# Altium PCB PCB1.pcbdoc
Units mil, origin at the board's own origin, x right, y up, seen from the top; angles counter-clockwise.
Board outline 1100 x 2012.93 mil, 2 copper layers (Top Layer, Bottom Layer); 25 components, 17 nets, 61 pads, 18 vias.
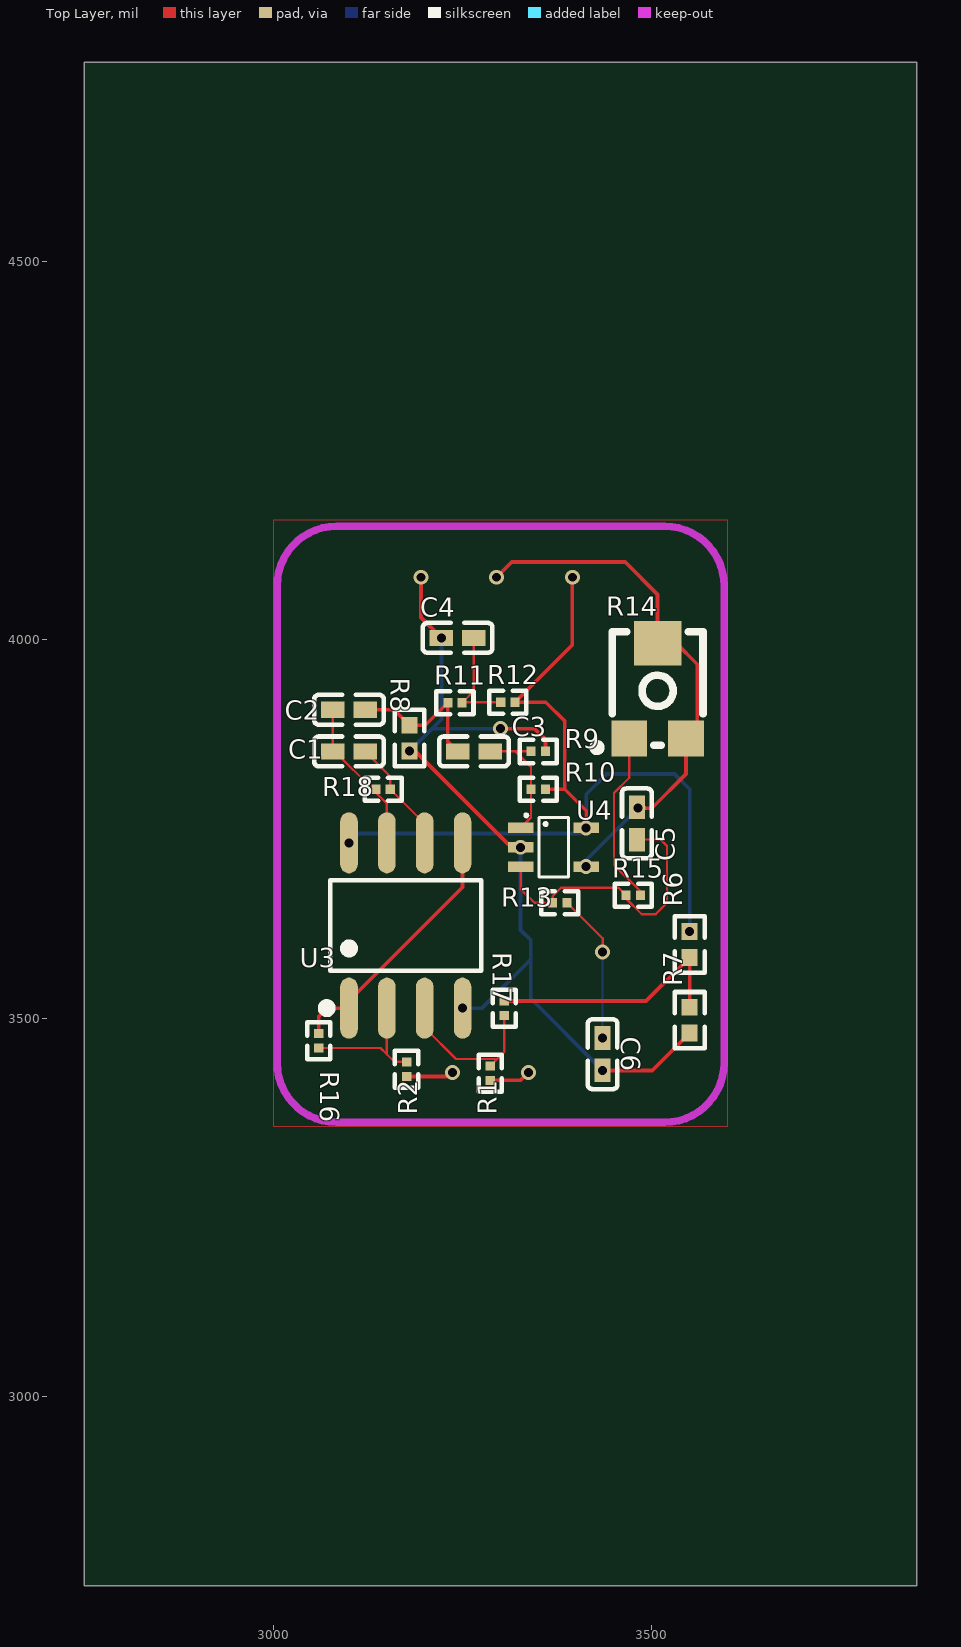
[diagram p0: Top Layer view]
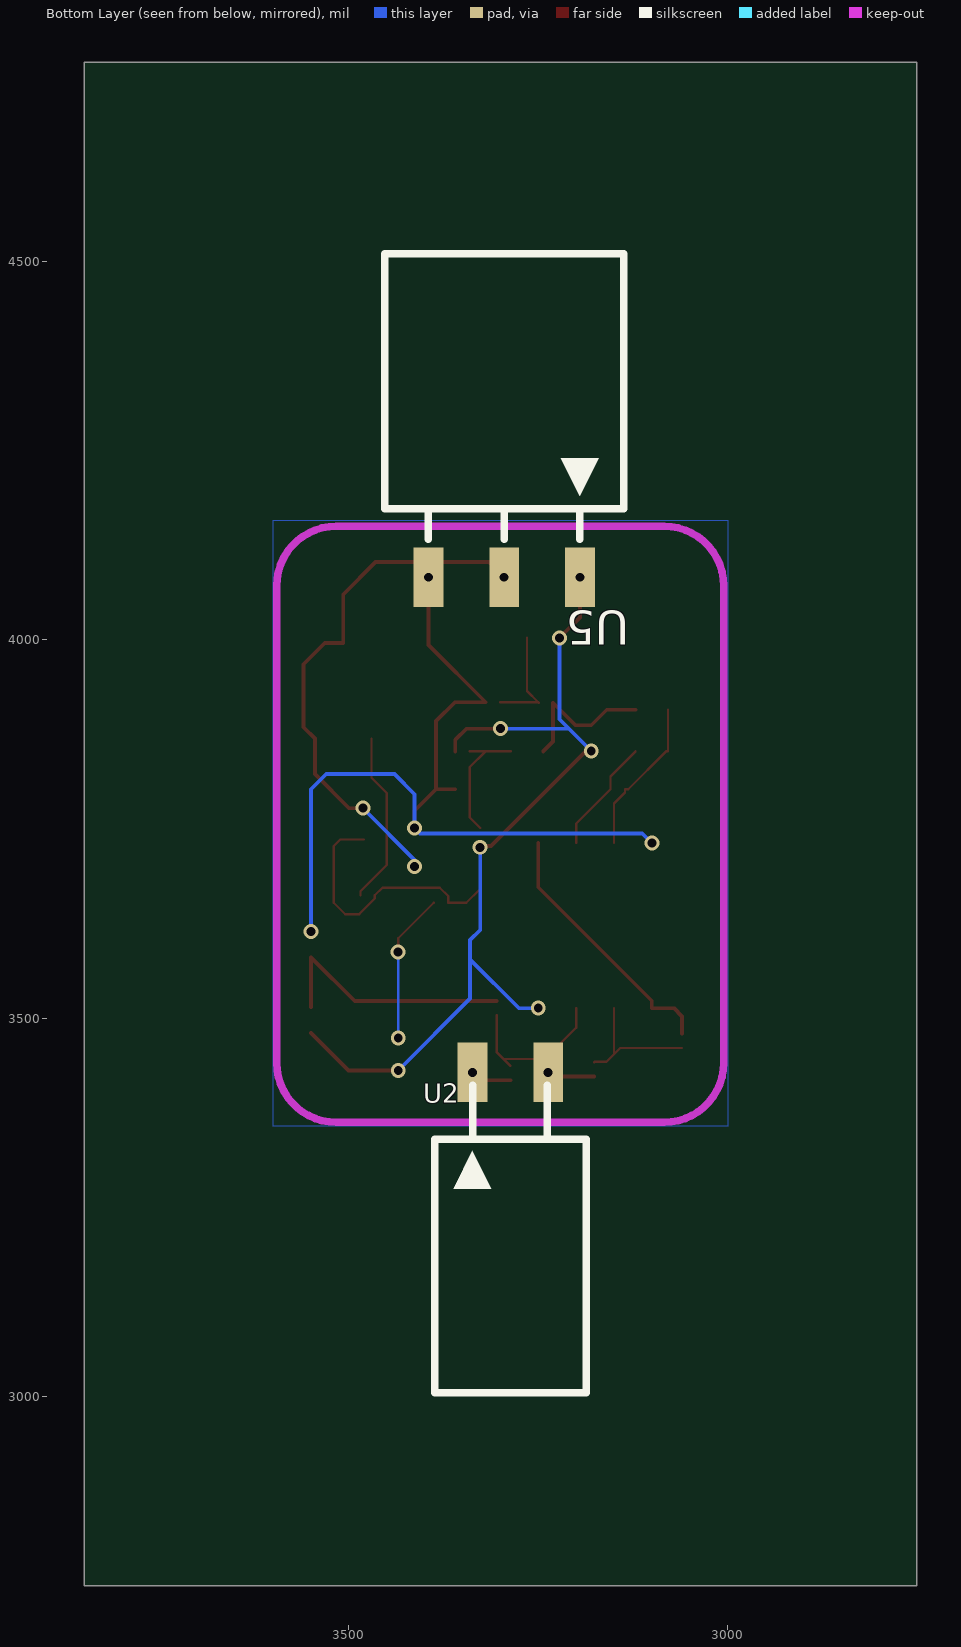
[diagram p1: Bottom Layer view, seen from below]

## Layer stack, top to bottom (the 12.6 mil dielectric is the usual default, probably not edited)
Top Layer: signal copper (thickness not stored)
Dielectric: dielectric 12.6, FR-4, Dk 4.8
Bottom Layer: signal copper (thickness not stored)

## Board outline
3850,2750 2750,2750 2750,4762.93 3850,4762.93

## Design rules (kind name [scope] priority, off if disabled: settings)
Clearance copperThickness1oz [All] p1: gap=7 ignorepadtopadclearanceinfootprint=FALSE except(4: Track-Track; 6: Track-SMDPad SMDPad-SMDPad Track-THPad SMDPad-THPad THPad-THPad Track-Via SMDPad-Via THPad-Via Via-Via Track-Fill SMDPad-Fill THPad-Fill Via-Fill Fill-Fill SMDPad-Region THPad-Region Via-Region Fill-Region Region-Region Track-Poly SMDPad-Poly THPad-Poly Via-Poly Fill-Poly Poly-Poly Track-Text SMDPad-Text THPad-Text Via-Text Fill-Text Region-Text Poly-Text Text-Text Track-Hole SMDPad-Hole THPad-Hole Via-Hole Fill-Hole Region-Hole Poly-Hole Text-Hole; 11.8: Track-Region Region-Poly Track-Sheet SMDPad-Sheet THPad-Sheet Via-Sheet Fill-Sheet Region-Sheet Poly-Sheet Text-Sheet Sheet-Hole)
Clearance copperThickness2oz [All] p1: gap=7 ignorepadtopadclearanceinfootprint=FALSE except(6: Track-SMDPad SMDPad-SMDPad Track-THPad SMDPad-THPad THPad-THPad Track-Via SMDPad-Via THPad-Via Via-Via Track-Fill SMDPad-Fill THPad-Fill Via-Fill Fill-Fill SMDPad-Region THPad-Region Via-Region Fill-Region Region-Region Track-Poly SMDPad-Poly THPad-Poly Via-Poly Fill-Poly Poly-Poly Track-Text SMDPad-Text THPad-Text Via-Text Fill-Text Region-Text Poly-Text Text-Text Track-Hole SMDPad-Hole THPad-Hole Via-Hole Fill-Hole Region-Hole Poly-Hole Text-Hole; 8: Track-Track; 11.8: Track-Region Region-Poly Track-Sheet SMDPad-Sheet THPad-Sheet Via-Sheet Fill-Sheet Region-Sheet Poly-Sheet Text-Sheet Sheet-Hole)
DiffPairsRouting differentialPair [All] p1: maxuncoupledlength=10 maxlimit=6 mostfreqgap=6 toplayer_minwidth=5 toplayer_prefwidth=10 toplayer_maxwidth=100 bottomlayer_minwidth=5 bottomlayer_prefwidth=10 bottomlayer_maxwidth=100
PasteMaskExpansion pasteMaskExpansion [All] p1:
PlaneConnect innerPlane [All] p1: planeconnectstyle=Relief reliefexpansion=20 reliefentries=4 reliefconductorwidth=10 reliefairgap=10
PolygonConnect copperRegion [All] p1: connectstyle=Relief reliefentries=4 reliefconductorwidth=10 polygonreliefangle="90 Angle" airgapwidth=10
RoutingVias viaSize [All] p1: viastyle="Through Hole" holewidth=11.8 minholewidth=11.8 maxholewidth=248 width=19.7 minwidth=19.7 maxwidth=393.7
SolderMaskExpansion solderMaskExpansion [All] p1: useseparateexpansions=TRUE expansion=2 expansionbottom=2
Width copperThickness1oz [All] p1: maxlimit=4 minlimit=3 preferedwidth=4
Width copperThickness2oz [All] p1: maxlimit=6 minlimit=5 preferedwidth=6

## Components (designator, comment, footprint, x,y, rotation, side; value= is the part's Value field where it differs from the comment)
C1 "CC0402JRNPO9BN100" C0402 3100,3852.38 r180 top
C2 "CL05A105KP5NNNC" C0402 3100,3907.38 r0 top
C3 "CC0402KRX7R9BB103" C0402 3265,3852.38 r0 top
C4 "CC0402KRX7R7BB104" C0402 3243.47,4002.38 r0 top
C5 "GRM1555C1H101JA01D" C0402 3480.22,3757.38 r90 top
C6 "GRM155R60J106ME44D" C0402 3434.96,3452.38 r90 top
R1 "0201WMF1002TEE" R0201 3286.53,3427.38 r90 top
R2 "0201WMF1002TEE" R0201 3176.07,3432.38 r90 top
R6 "0402WGF3001TCE" R0402 3550,3597.38 r90 top
R7 "0402WGF1001TCE" R0402 3550,3497.38 r90 top
R8 "0402WGF8201TCE" R0402 3180,3869.92 r90 top
R9 "RC0201FR-071ML" R0201 3350,3852.38 r180 top
R10 "RC0201FR-071ML" R0201 3350,3802.38 r0 top
R11 "0201WMF1001TEE" R0201 3240,3916.72 r0 top
R12 "0201WMF1001TEE" R0201 3309.95,3917.38 r0 top
R13 "0201WMF1001TEE" R0201 3378.51,3652.38 r180 top
R14 "TC33X-2-104E" RES-ADJ-SMD_TC33X-2-104E 3507.63,3932.38 r0 top
R15 "RC0201FR-0722KL" R0201 3475.37,3662.38 r0 top
R16 "RC0201FR-07200KL" R0201 3060,3470.1 r90 top
R17 "RC0201FR-07200KL" R0201 3305,3513.23 r270 top
R18 "0201WMF2004TEE" R0201 3145,3802.38 r180 top
U2 "X6511FRS-02-C85D30" HDR-SMD_2P-P2.54-H-F-L11.5 3286.89,3428.5 r180 bottom
U3 "LM358BAIDR" SOIC-8_L4.9-W3.9-P1.27-LS6.0-BL 3175,3622.38 r0 top
U4 "MAX4466EXK+T" SC-70-5_L2.0-W1.3-P0.65-LS2.1-BR 3370,3725.72 r180 top
U5 "X6511FRS-03-C85D30" HDR-SMD_3P-P2.54-H-F-L11.5 3295,4082.38 r0 bottom

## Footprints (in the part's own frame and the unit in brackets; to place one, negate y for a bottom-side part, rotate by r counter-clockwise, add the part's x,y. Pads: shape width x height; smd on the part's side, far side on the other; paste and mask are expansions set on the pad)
C0402 [mm]
  rect 0.79x0.54 smd: 1(-0.545,0) 2(0.545,0)
  silkscreen extent -1.17,-0.5 1.17,0.5
HDR-SMD_2P-P2.54-H-F-L11.5 [mm]
  rect 1x2 smd: 1(-1.27,0) 2(1.27,0)
  silkscreen extent -2.54,-10.76 2.54,-0.43
HDR-SMD_3P-P2.54-H-F-L11.5 [mm]
  rect 1x2 smd: 1(-2.54,0) 2(0,0) 3(2.54,0)
  silkscreen extent -4.01,-10.86 4.01,-1.27
R0201 [mil]
  rect 11.93x12.76 smd: 1(-9.51,0) 2(9.51,0)
  silkscreen extent -24,-15 24,15
R0402 [mm]
  rect 0.566x0.54 smd: 1(-0.433,0) 2(0.433,0)
  silkscreen extent -0.94,-0.5 0.94,0.5
RES-ADJ-SMD_TC33X-2-104E [mm]
  rect 1.2x1.2 smd: 1(-0.95,-1.6) 3(0.95,-1.6)
  rect 1.6x1.5 smd: 2(0,1.6)
  silkscreen extent -2.16,-2.03 1.52,1.98
SC-70-5_L2.0-W1.3-P0.65-LS2.1-BR [mm]
  rect 0.85x0.35 smd: 1(1.1,-0.65) 2(1.1,0) 3(1.1,0.65) 4(-1.1,0.65) 5(-1.1,-0.65)
  silkscreen extent -0.5,-1.12 0.96,1
SOIC-8_L4.9-W3.9-P1.27-LS6.0-BL [mm]
  oval 0.588x2.045 smd: 1(-1.905,-2.772) 2(-0.635,-2.772) 3(0.635,-2.772) 4(1.905,-2.772) 5(1.905,2.772) 6(0.635,2.772) 7(-0.635,2.772) 8(-1.905,2.772)
  silkscreen extent -2.8,-2.92 2.53,1.52

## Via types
v1: diameter 19.7, hole 11.81, Top Layer to Bottom Layer, 17 vias
v2: diameter 19.68, hole 11.81, Top Layer to Bottom Layer, 1 vias

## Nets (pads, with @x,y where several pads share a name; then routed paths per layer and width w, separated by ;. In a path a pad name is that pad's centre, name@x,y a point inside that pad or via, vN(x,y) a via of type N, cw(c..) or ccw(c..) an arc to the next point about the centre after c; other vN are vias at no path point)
$1N688: R1.2 R17.2 U3.3 | length 213.2
  Top Layer w3: U3.3 3200,3487.38 3241.24,3446.14 3295.78,3446.14 ; R1.2 3295.78,3446.14 ; R17.2 3305,3455.35 3295.78,3446.14
$1N766: R2.2 R16.1 U3.2 | length 184.7
  Top Layer w3: R16.1 3141.79,3460.59 3150,3452.38 ; U3.2 3150,3452.38 ; R2.2 3175.59,3442.38 3160,3442.38 3150,3452.38
$1N988: C1.1 R18.1 U3.6 | length 153.4
  Top Layer w3: C1.1 3154.51,3819.33 R18.1 3200,3756.89 U3.6
$1N2751: C4.2 R11.2 R12.1 | length 142.3
  Top Layer w3: R11.2 R11.2@3250.17,3917.38 ; C4.2 3264.93,3932.14 R11.2@3250.17,3917.38 ; R12.1 R11.2@3250.17,3917.38
$1N2818: C3.2 R9.2 R10.1 U4.1 | length 169.4
  Top Layer w3: C3.2 3319.8,3852.38 ; U4.1 3340.49,3765.11 R10.1 3340.49,3831.69 3319.8,3852.38 ; R9.2 3319.8,3852.38
$1N3169: C6.2 R13.1 | length 198
  Top Layer w3: R13.1 3435,3605.4 v1(3435,3587.38)
  Bottom Layer w3: v1(3434.96,3473.84) v1@3434.96,3587.34
$1N3329: C5.1 R13.2 R15.1 U4.3 | length 385.4
  Top Layer w3: U4.3 3326.69,3670.69 3345,3652.38 R13.2 3369,3661.38 3380,3672.38 3455.86,3672.38 R15.1 3465.86,3658.14 3486.62,3637.38 3505,3637.38 3520,3652.38 3520,3727.38 3511.46,3735.92 C5.1
$1N3336: R14.1 R15.2 | length 229.8
  Top Layer w3: R14.1 3470.23,3817.61 3450,3797.38 3450,3702.38 3484.88,3667.5 R15.2
$1N3656: C1.2 C2.1 R18.2 U3.7 | length 209.5
  Top Layer w3: C2.1 C1.2 3081.25,3852.38 3131.25,3802.38 R18.2 3135.49,3798.14 3150,3783.63 U3.7
AGND: C4.1 C6.1 R7.1 R8.1 R9.1 U3.4 U4.2 U5.1 | length 1219.9
  Top Layer w5: v1(3180,3852.88) 3187.07,3852.88 3312.58,3727.38 3325.03,3727.38 v1(3326.69,3725.72) ; v1(3195,4082.38) 3195,4029.38 v1(3222.01,4002.38) ; v1(3300,3882.38) 3345,3882.38 3359.51,3867.87 R9.1 ; v1(3434.96,3430.92) 3500.58,3430.92 R7.1
  Bottom Layer w5: v1(3180,3852.88) 3210.76,3883.64 ; v1(3222.01,4002.38) 3222.01,3894.89 3210.76,3883.64 ; v1(3250,3513.23) 3275.85,3513.23 3340,3577.38 ; v1(3300,3882.38) 3212.02,3882.38 3210.76,3883.64 ; v1(3326.69,3725.72) 3326.69,3616.54 3340,3603.23 3340,3577.38 ; v1(3434.96,3430.92) 3340,3525.88 3340,3577.38
V_F: C2.2 C3.1 R8.2 R11.1 | length 199.6
  Top Layer w5: C2.2 3159.59,3907.38 R8.2 3200.73,3886.96 R11.1 3230.49,3865.43 C3.1
V_OUT: C5.2 R14.2 R14.3 U4.4 U5.2 | length 707.7
  Top Layer w5: v1(3295,4082.38) 3315,4102.38 3465,4102.38 3507.63,4059.75 R14.2 3532.01,3995.37 3560,3967.38 3560,3884.35 R14.3 3545.03,3822.41 3500,3777.38 v1(3481.68,3777.38) C5.2
  Bottom Layer w5: v1(3413.31,3700.13) 3413.31,3709.01 v1(3481.68,3777.38)
V_REF: R6.1 R7.2 R17.1 | length 334.8
  Top Layer w5: R17.1 3492.41,3522.74 R6.1 R7.2
VCC: R6.2 R10.2 R12.2 U3.8 U4.5 U5.3 | length 1160.3
  Top Layer w5: R10.2 3385,3802.38 ; v1(3395,4082.38) 3395,3992.92 R12.2 3360,3917.38 3385,3892.38 3385,3802.38 ; v1(3413.31,3751.31) 3413.31,3774.07 3385,3802.38
  Bottom Layer w5: v1(3100,3731.53) 3112.54,3744.07 3406.07,3744.07 v1(3413.31,3751.31) 3413.31,3795.69 3440,3822.38 3530,3822.38 3550,3802.38 v1(3550,3614.42)
VIN1: R2.1 U2.2 | length 63.1
  Top Layer w5: R2.1 3231.26,3422.87 v1(3236.89,3428.5)
VIN2: 
VO1: R16.2 U3.1 U3.5 | length 347.7
  Top Layer w5: R16.2 3060,3502.38 3070.85,3513.23 U3.1 3100,3523.04 3250,3673.04 U3.5
pads on no net: R1.1 U2.1
copper on no net: | length 54.8
  Top Layer w5: 3286.53,3417.87 3326.26,3417.87 v2(3336.89,3428.5)

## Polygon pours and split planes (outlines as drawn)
AGND on Top Layer (solid, remove dead copper): 3000,3357.38 3600,3357.38 3600,4157.38 3000,4157.38
AGND on Bottom Layer (solid, remove dead copper, pour order 4): 3000,3357.38 3600,3357.38 3600,4157.38 3000,4157.38

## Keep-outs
Board Outline Layer:
  lines w10: 3005,3441.12 ccw(c3083.74,3441.12) 3083.74,3362.38 3516.81,3362.38 ccw(c3516.81,3441.12) 3595.55,3441.12 3595.55,4071.04 ccw(c3516.81,4071.04) 3516.81,4149.78 3083.74,4149.78 ccw(c3083.74,4071.04) 3005,4071.04 3005,3441.12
